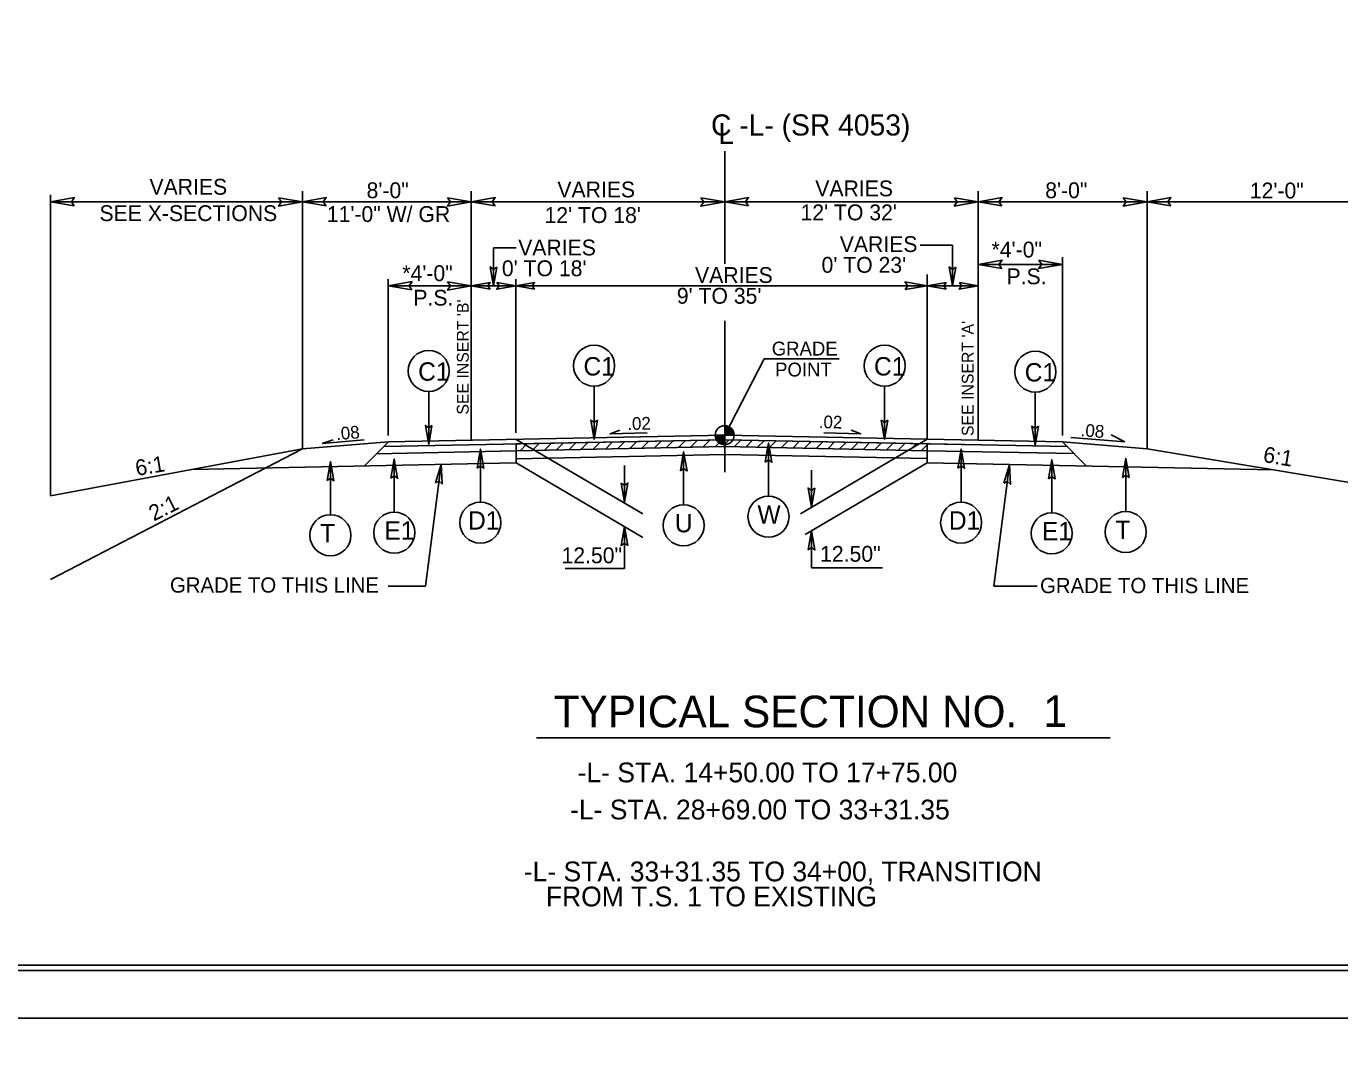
# Model space of a CAD drawing. Extents: x 981824 to 982276, y 44828 to 45204.
# Drawn here: x 982136.62 to 982186.38, y 45089.07 to 45127.55 of the extents above; entities that cross this region are included whole.
import ezdxf

# ---------------------------------------------------------------- set-up
doc = ezdxf.new("R2010")
doc.units = 0
for name, color, linetype in [('Default', 7, 'Continuous'), ('Old_Level_1', 7, 'Continuous'), ('Old_Level_11', 7, 'Continuous'), ('Old_Level_18', 7, 'Continuous'), ('Old_Level_2', 7, 'Continuous'), ('Old_Level_20', 7, 'Continuous'), ('Old_Level_21', 7, 'Continuous'), ('Old_Level_3', 7, 'Continuous'), ('Old_Level_50', 7, 'Continuous'), ('Old_Level_51', 7, 'Continuous'), ('Prop Dimension Text', 7, 'Continuous'), ('Prop Roadway Profile Bench Mark Info Text', 7, 'Continuous'), ('Typical Terminator CELL', 7, 'Continuous')]:
    doc.layers.add(name, color=color, linetype=linetype)

msp = doc.modelspace()

# ---------------------------------------------------------------- linework, layer by layer
at = {"layer": 'Default'}
for points in [[(982160.143, 45112.149), (982158.742, 45112.101), (982159.108, 45112.239)], [(982166.835, 45112.149), (982168.235, 45112.101), (982167.869, 45112.239)]]:
    msp.add_lwpolyline(points, dxfattribs=at)
at = {"layer": 'Old_Level_1'}
for p, q in [((982163.083, 45122.815), (982163.083, 45118.548)), ((982137.545, 45121.166), (982137.545, 45109.759)), ((982147.083, 45121.294), (982147.083, 45111.537)), ((982153.483, 45121.294), (982153.483, 45111.86)), ((982172.683, 45121.294), (982172.683, 45120.151)), ((982179.083, 45121.294), (982179.083, 45111.54)), ((982137.545, 45120.894), (982147.083, 45120.894)), ((982147.083, 45120.894), (982153.483, 45120.894)), ((982153.483, 45120.894), (982163.083, 45120.894)), ((982163.083, 45120.894), (982172.683, 45120.894)), ((982172.683, 45120.894), (982179.083, 45120.894)), ((982179.083, 45120.894), (982188.683, 45120.894)), ((982172.683, 45120.151), (982172.683, 45118.526)), ((982154.324, 45117.712), (982154.324, 45119.158)), ((982154.324, 45119.158), (982155.184, 45119.158)), ((982170.481, 45119.249), (982171.716, 45119.249)), ((982171.716, 45119.249), (982171.716, 45117.712)), ((982175.881, 45118.803), (982175.881, 45117.486)), ((982170.757, 45118.144), (982170.757, 45117.695)), ((982172.683, 45118.526), (982175.881, 45118.526)), ((982172.683, 45118.526), (982172.683, 45117.497)), ((982150.334, 45117.968), (982150.334, 45112.046)), ((982150.334, 45117.712), (982153.483, 45117.712)), ((982153.483, 45117.712), (982155.165, 45117.712)), ((982155.165, 45117.968), (982155.165, 45112.144)), ((982155.165, 45117.712), (982166.471, 45117.712)), ((982166.471, 45117.712), (982170.757, 45117.712)), ((982170.757, 45117.712), (982172.683, 45117.712)), ((982170.757, 45117.695), (982170.757, 45116.956)), ((982172.683, 45117.497), (982172.683, 45111.86)), ((982175.881, 45117.486), (982175.881, 45112.045)), ((982170.757, 45116.956), (982170.757, 45111.899)), ((982163.083, 45116.381), (982163.083, 45110.647)), ((982163.083, 45112.052), (982164.573, 45114.947)), ((982163.083, 45112.052), (982163.083, 45112.412)), ((982147.083, 45111.537), (982150.344, 45111.798)), ((982147.832, 45111.736), (982149.429, 45111.878)), ((982147.832, 45111.736), (982148.254, 45111.878)), ((982150.344, 45111.798), (982149.427, 45110.886)), ((982163.083, 45112.052), (982150.344, 45111.798)), ((982155.177, 45111.895), (982159.983, 45109.074)), ((982155.177, 45111.723), (982163.083, 45111.88)), ((982155.177, 45111.723), (982163.083, 45111.88)), ((982155.177, 45111.002), (982155.177, 45111.723)), ((982155.329, 45111.465), (982155.593, 45111.73)), ((982155.79, 45111.475), (982156.055, 45111.74)), ((982156.252, 45111.484), (982156.517, 45111.748)), ((982156.713, 45111.493), (982156.978, 45111.758)), ((982157.176, 45111.503), (982157.441, 45111.767)), ((982157.637, 45111.512), (982157.902, 45111.776)), ((982158.099, 45111.521), (982158.364, 45111.786)), ((982158.561, 45111.53), (982158.825, 45111.795)), ((982159.023, 45111.54), (982159.288, 45111.804)), ((982159.485, 45111.549), (982159.749, 45111.813)), ((982159.946, 45111.558), (982160.211, 45111.823)), ((982160.409, 45111.568), (982160.673, 45111.832)), ((982160.87, 45111.576), (982161.135, 45111.841)), ((982161.332, 45111.586), (982161.597, 45111.851)), ((982161.793, 45111.596), (982162.058, 45111.86)), ((982162.256, 45111.604), (982162.521, 45111.869)), ((982162.717, 45111.614), (982162.982, 45111.878)), ((982162.723, 45112.052), (982163.083, 45112.052)), ((982163.076, 45111.698), (982163.255, 45111.878)), ((982163.082, 45111.692), (982163.083, 45112.052)), ((982163.083, 45112.052), (982163.082, 45111.692)), ((982163.083, 45112.052), (982175.881, 45111.796)), ((982163.443, 45112.052), (982163.083, 45112.052)), ((982163.083, 45111.88), (982172.683, 45111.688)), ((982163.443, 45111.613), (982163.699, 45111.868)), ((982163.887, 45111.604), (982164.142, 45111.86)), ((982164.33, 45111.595), (982164.586, 45111.851)), ((982164.774, 45111.586), (982165.03, 45111.842)), ((982165.217, 45111.577), (982165.473, 45111.833)), ((982165.661, 45111.568), (982165.917, 45111.824)), ((982170.757, 45111.899), (982165.951, 45109.078)), ((982166.105, 45111.56), (982166.361, 45111.816)), ((982166.549, 45111.551), (982166.805, 45111.807)), ((982166.993, 45111.542), (982167.248, 45111.797)), ((982167.436, 45111.533), (982167.692, 45111.788)), ((982167.88, 45111.524), (982168.136, 45111.78)), ((982168.323, 45111.515), (982168.579, 45111.771)), ((982168.767, 45111.506), (982169.023, 45111.762)), ((982169.21, 45111.497), (982169.466, 45111.753)), ((982169.654, 45111.488), (982169.91, 45111.744)), ((982170.098, 45111.48), (982170.353, 45111.736)), ((982170.541, 45111.471), (982170.757, 45111.685)), ((982170.757, 45111.007), (982170.757, 45111.727)), ((982170.757, 45111.466), (982170.757, 45111.727)), ((982175.881, 45111.796), (982179.083, 45111.54)), ((982175.881, 45111.796), (982176.792, 45110.886)), ((982178.235, 45111.806), (982176.197, 45111.969)), ((982178.235, 45111.806), (982177.725, 45112.061)), ((982137.545, 45106.58), (982147.083, 45111.537)), ((982137.545, 45109.759), (982147.083, 45111.537)), ((982155.177, 45111.462), (982149.894, 45111.351)), ((982163.089, 45111.621), (982155.171, 45111.462)), ((982163.094, 45111.324), (982155.177, 45111.164)), ((982163.069, 45111.323), (982170.757, 45111.168)), ((982163.074, 45111.62), (982170.757, 45111.466)), ((982170.757, 45111.466), (982176.323, 45111.355)), ((982179.083, 45111.54), (982188.683, 45109.944)), ((982155.181, 45111.002), (982142.882, 45110.754)), ((982151.748, 45106.333), (982152.342, 45110.945)), ((982155.181, 45111.002), (982159.986, 45108.182)), ((982159.286, 45110.907), (982159.286, 45109.518)), ((982170.757, 45111.007), (982166.125, 45108.288)), ((982166.37, 45110.724), (982166.37, 45109.324)), ((982170.757, 45111.007), (982183.876, 45110.744)), ((982173.28, 45106.333), (982173.875, 45110.944)), ((982159.286, 45108.592), (982159.286, 45107.003)), ((982166.37, 45108.432), (982166.37, 45107.032)), ((982157.041, 45107.003), (982159.286, 45107.003)), ((982169.06, 45107.032), (982166.37, 45107.032)), ((982150.329, 45106.333), (982151.748, 45106.333)), ((982173.28, 45106.333), (982174.919, 45106.333))]:
    msp.add_line(p, q, dxfattribs=at)
for points in [[(982163.086, 45112.412), (982163.086, 45112.412), (982163.086, 45112.052)], [(982163.093, 45112.412), (982163.093, 45112.052)], [(982163.101, 45112.412), (982163.101, 45112.052)], [(982163.108, 45112.412), (982163.108, 45112.052)], [(982163.115, 45112.411), (982163.115, 45112.052)], [(982163.122, 45112.41), (982163.122, 45112.052)], [(982163.129, 45112.409), (982163.129, 45112.052)], [(982163.137, 45112.408), (982163.137, 45112.052)], [(982163.144, 45112.408), (982163.144, 45112.052)], [(982163.151, 45112.406), (982163.151, 45112.052)], [(982163.158, 45112.404), (982163.158, 45112.052)], [(982163.165, 45112.403), (982163.165, 45112.052)], [(982163.173, 45112.401), (982163.173, 45112.052)], [(982163.18, 45112.399), (982163.18, 45112.052)], [(982163.187, 45112.397), (982163.187, 45112.052)], [(982163.194, 45112.395), (982163.194, 45112.052)], [(982163.201, 45112.392), (982163.201, 45112.052)], [(982163.209, 45112.39), (982163.209, 45112.052)], [(982163.216, 45112.387), (982163.216, 45112.052)], [(982163.223, 45112.384), (982163.223, 45112.052)], [(982163.23, 45112.38), (982163.23, 45112.052)], [(982163.237, 45112.377), (982163.237, 45112.052)], [(982163.245, 45112.374), (982163.245, 45112.052)], [(982163.252, 45112.37), (982163.252, 45112.052)], [(982163.259, 45112.366), (982163.259, 45112.052)], [(982163.266, 45112.362), (982163.266, 45112.052)], [(982163.273, 45112.358), (982163.273, 45112.052)], [(982163.281, 45112.353), (982163.281, 45112.052)], [(982163.288, 45112.348), (982163.288, 45112.052)], [(982163.295, 45112.343), (982163.295, 45112.052)], [(982163.302, 45112.338), (982163.302, 45112.052)], [(982163.309, 45112.332), (982163.309, 45112.052)], [(982163.317, 45112.326), (982163.317, 45112.052)], [(982163.324, 45112.32), (982163.324, 45112.052)], [(982163.331, 45112.313), (982163.331, 45112.052)], [(982163.338, 45112.306), (982163.338, 45112.052)], [(982163.345, 45112.299), (982163.345, 45112.052)], [(982163.353, 45112.291), (982163.353, 45112.052)], [(982163.36, 45112.282), (982163.36, 45112.052)], [(982163.367, 45112.273), (982163.367, 45112.052)], [(982163.374, 45112.264), (982163.374, 45112.052)], [(982163.381, 45112.253), (982163.381, 45112.052)], [(982163.389, 45112.242), (982163.389, 45112.052)], [(982163.396, 45112.23), (982163.396, 45112.052)], [(982163.403, 45112.217), (982163.403, 45112.052)], [(982163.41, 45112.202), (982163.41, 45112.052)], [(982163.417, 45112.185), (982163.417, 45112.052)], [(982162.725, 45112.052), (982162.725, 45112.013)], [(982162.732, 45112.052), (982162.732, 45111.971)], [(982162.739, 45112.052), (982162.739, 45111.945)], [(982162.746, 45112.052), (982162.746, 45111.924)], [(982162.753, 45112.052), (982162.753, 45111.907)], [(982162.761, 45112.052), (982162.761, 45111.892)], [(982162.768, 45112.052), (982162.768, 45111.878)], [(982162.775, 45112.052), (982162.775, 45111.865)], [(982162.782, 45112.052), (982162.782, 45111.854)], [(982162.789, 45112.052), (982162.789, 45111.844)], [(982162.797, 45112.052), (982162.797, 45111.834)], [(982162.804, 45112.052), (982162.804, 45111.825)], [(982162.811, 45112.052), (982162.811, 45111.816)], [(982162.818, 45112.052), (982162.818, 45111.808)], [(982162.825, 45112.052), (982162.825, 45111.8)], [(982162.833, 45112.052), (982162.833, 45111.793)], [(982162.84, 45112.052), (982162.84, 45111.787)], [(982162.847, 45112.052), (982162.847, 45111.78)], [(982162.854, 45112.052), (982162.854, 45111.774)], [(982162.861, 45112.052), (982162.861, 45111.768)], [(982162.869, 45112.052), (982162.869, 45111.763)], [(982162.876, 45112.052), (982162.876, 45111.758)], [(982162.883, 45112.052), (982162.883, 45111.753)], [(982162.89, 45112.052), (982162.89, 45111.748)], [(982162.897, 45112.052), (982162.897, 45111.744)], [(982162.905, 45112.052), (982162.905, 45111.74)], [(982162.912, 45112.052), (982162.912, 45111.736)], [(982162.919, 45112.052), (982162.919, 45111.732)], [(982162.926, 45112.052), (982162.926, 45111.728)], [(982162.933, 45112.052), (982162.933, 45111.725)], [(982162.941, 45112.052), (982162.941, 45111.722)], [(982162.948, 45112.052), (982162.948, 45111.719)], [(982162.955, 45112.052), (982162.955, 45111.716)], [(982162.962, 45112.052), (982162.962, 45111.713)], [(982162.969, 45112.052), (982162.969, 45111.711)], [(982162.977, 45112.052), (982162.977, 45111.708)], [(982162.984, 45112.052), (982162.984, 45111.707)], [(982162.991, 45112.052), (982162.991, 45111.704)], [(982162.998, 45112.052), (982162.998, 45111.703)], [(982163.005, 45112.052), (982163.005, 45111.701)], [(982163.013, 45112.052), (982163.013, 45111.7)], [(982163.02, 45112.052), (982163.02, 45111.698)], [(982163.027, 45112.052), (982163.027, 45111.697)], [(982163.034, 45112.052), (982163.034, 45111.696)], [(982163.041, 45112.052), (982163.041, 45111.695)], [(982163.049, 45112.052), (982163.049, 45111.694)], [(982163.056, 45112.052), (982163.056, 45111.693)], [(982163.063, 45112.052), (982163.063, 45111.693)], [(982163.07, 45112.052), (982163.07, 45111.692)], [(982163.077, 45112.052), (982163.077, 45111.692), (982163.077, 45111.692)], [(982163.425, 45112.165), (982163.425, 45112.052)], [(982163.432, 45112.14), (982163.432, 45112.052)], [(982163.439, 45112.104), (982163.439, 45112.052)]]:
    msp.add_lwpolyline(points, dxfattribs=at)
for points in [[(982155.177, 45111.462), (982163.089, 45111.621), (982163.083, 45111.88), (982155.177, 45111.723)], [(982163.074, 45111.62), (982170.757, 45111.466), (982170.757, 45111.727), (982163.08, 45111.881)]]:
    msp.add_lwpolyline(points, close=True, dxfattribs=at)
msp.add_circle((982163.082, 45112.053), 0.36, dxfattribs=at)
for start, end in [(359.9905, 89.9905), (179.9905, 269.9905)]:
    msp.add_arc((982163.082, 45112.053), 0.36, start, end, dxfattribs=at)
at = {"layer": 'Old_Level_11'}
for points in [[(982169.916, 45117.568), (982170.757, 45117.712), (982169.911, 45117.862), (982170.018, 45117.712)], [(982151.994, 45112.422), (982151.87, 45111.702), (982151.742, 45112.426), (982151.87, 45112.334)], [(982158.259, 45112.618), (982158.135, 45111.898), (982158.007, 45112.622), (982158.135, 45112.53)], [(982169.264, 45112.618), (982169.14, 45111.898), (982169.012, 45112.622), (982169.14, 45112.53)], [(982174.974, 45112.392), (982174.85, 45111.672), (982174.722, 45112.396), (982174.85, 45112.304)], [(982164.619, 45111.035), (982164.743, 45111.755), (982164.871, 45111.031), (982164.743, 45111.123)], [(982153.703, 45110.808), (982153.827, 45111.528), (982153.955, 45110.804), (982153.827, 45110.896)], [(982161.403, 45110.706), (982161.527, 45111.426), (982161.655, 45110.702), (982161.527, 45110.794)], [(982171.916, 45110.808), (982172.04, 45111.528), (982172.168, 45110.804), (982172.04, 45110.896)], [(982178.149, 45110.456), (982178.273, 45111.176), (982178.401, 45110.452), (982178.273, 45110.544)], [(982148.024, 45110.331), (982148.148, 45111.051), (982148.276, 45110.327), (982148.148, 45110.419)], [(982150.44, 45110.429), (982150.564, 45111.149), (982150.692, 45110.425), (982150.564, 45110.517)], [(982175.347, 45110.402), (982175.471, 45111.122), (982175.599, 45110.398), (982175.471, 45110.49)]]:
    msp.add_lwpolyline(points, close=True, dxfattribs=at)
at = {"layer": 'Old_Level_18'}
msp.add_lwpolyline([(982227.72, 45175.969), (982107.72, 45175.969), (982107.72, 45091.969), (982227.72, 45091.969)], close=True, dxfattribs=at)
at = {"layer": 'Old_Level_21'}
for points in [[(982163.083, 45111.88), (982150.168, 45111.623), (982150.344, 45111.798), (982163.083, 45112.052)], [(982163.083, 45112.052), (982175.881, 45111.796), (982176.057, 45111.621), (982163.08, 45111.88)]]:
    msp.add_lwpolyline(points, close=True, dxfattribs=at)
at = {"layer": 'Old_Level_3'}
msp.add_line((982164.573, 45114.947), (982167.419, 45114.947), dxfattribs=at)
at = {"layer": 'Old_Level_50'}
msp.add_lwpolyline([(982228.72, 45176.173), (982095.4, 45176.173), (982095.4, 45091.765), (982228.72, 45091.765)], close=True, dxfattribs=at)
at = {"layer": 'Old_Level_51'}
for points in [[(982229.08, 45177.969), (982094.36, 45177.969), (982094.36, 45089.969), (982229.08, 45089.969)], [(982229.08, 45089.969), (982094.36, 45089.969), (982094.36, 45001.969), (982229.08, 45001.969)]]:
    msp.add_lwpolyline(points, close=True, dxfattribs=at)
at = {"layer": 'Prop Dimension Text'}
for p, q in [((982151.87, 45113.711), (982151.87, 45111.702)), ((982158.135, 45113.908), (982158.135, 45111.898)), ((982169.14, 45113.908), (982169.14, 45111.898)), ((982174.85, 45113.681), (982174.85, 45111.672)), ((982164.743, 45109.745), (982164.743, 45111.755)), ((982153.827, 45109.519), (982153.827, 45111.528)), ((982161.527, 45109.416), (982161.527, 45111.426)), ((982172.04, 45109.519), (982172.04, 45111.528)), ((982178.273, 45109.166), (982178.273, 45111.176)), ((982148.148, 45109.041), (982148.148, 45111.051)), ((982150.564, 45109.139), (982150.564, 45111.149)), ((982175.471, 45109.112), (982175.471, 45111.122))]:
    msp.add_line(p, q, dxfattribs=at)
for centre in [(982151.87, 45114.488), (982158.135, 45114.685), (982169.14, 45114.685), (982174.85, 45114.459), (982164.742, 45108.967), (982153.826, 45108.74), (982161.526, 45108.637), (982172.039, 45108.74), (982148.146, 45108.263), (982150.563, 45108.361), (982175.47, 45108.335), (982178.272, 45108.388)]:
    msp.add_circle(centre, 0.778, dxfattribs=at)
at = {"layer": 'Prop Roadway Profile Bench Mark Info Text'}
msp.add_line((982155.959, 45100.582), (982177.679, 45100.582), dxfattribs=at)
at = {"layer": 'Typical Terminator CELL'}
for points in [[(982138.445, 45120.739), (982137.545, 45120.894), (982138.45, 45121.054), (982138.335, 45120.894)], [(982146.183, 45121.049), (982147.083, 45120.894), (982146.178, 45120.734), (982146.293, 45120.894)], [(982147.983, 45120.739), (982147.083, 45120.894), (982147.988, 45121.054), (982147.873, 45120.894)], [(982152.583, 45121.049), (982153.483, 45120.894), (982152.578, 45120.734), (982152.693, 45120.894)], [(982154.383, 45120.739), (982153.483, 45120.894), (982154.388, 45121.054), (982154.273, 45120.894)], [(982162.183, 45121.049), (982163.083, 45120.894), (982162.178, 45120.734), (982162.293, 45120.894)], [(982163.983, 45120.739), (982163.083, 45120.894), (982163.988, 45121.054), (982163.873, 45120.894)], [(982171.783, 45121.049), (982172.683, 45120.894), (982171.778, 45120.734), (982171.893, 45120.894)], [(982173.583, 45120.739), (982172.683, 45120.894), (982173.588, 45121.054), (982173.473, 45120.894)], [(982178.183, 45121.049), (982179.083, 45120.894), (982178.178, 45120.734), (982178.293, 45120.894)], [(982179.983, 45120.739), (982179.083, 45120.894), (982179.988, 45121.054), (982179.873, 45120.894)], [(982173.583, 45118.371), (982172.683, 45118.526), (982173.588, 45118.686), (982173.473, 45118.526)], [(982174.981, 45118.681), (982175.881, 45118.526), (982174.976, 45118.366), (982175.091, 45118.526)], [(982154.446, 45118.424), (982154.324, 45117.712), (982154.197, 45118.428), (982154.324, 45118.337)], [(982171.838, 45118.424), (982171.716, 45117.712), (982171.589, 45118.428), (982171.716, 45118.337)], [(982151.234, 45117.557), (982150.334, 45117.712), (982151.239, 45117.872), (982151.124, 45117.712)], [(982152.583, 45117.867), (982153.483, 45117.712), (982152.578, 45117.552), (982152.693, 45117.712)], [(982154.194, 45117.59), (982153.483, 45117.712), (982154.198, 45117.839), (982154.107, 45117.712)], [(982154.453, 45117.835), (982155.165, 45117.712), (982154.449, 45117.586), (982154.54, 45117.712)], [(982155.876, 45117.59), (982155.165, 45117.712), (982155.88, 45117.839), (982155.789, 45117.712)], [(982171.468, 45117.59), (982170.757, 45117.712), (982171.472, 45117.839), (982171.381, 45117.712)], [(982171.972, 45117.835), (982172.683, 45117.712), (982171.968, 45117.586), (982172.059, 45117.712)], [(982152.129, 45110.246), (982152.342, 45110.944), (982152.379, 45110.21), (982152.263, 45110.317)], [(982173.66, 45110.232), (982173.873, 45110.931), (982173.909, 45110.197), (982173.794, 45110.304)], [(982159.162, 45110.238), (982159.286, 45109.518), (982159.414, 45110.242), (982159.286, 45110.15)], [(982166.494, 45110.044), (982166.37, 45109.324), (982166.242, 45110.048), (982166.37, 45109.956)], [(982159.41, 45107.872), (982159.286, 45108.592), (982159.158, 45107.868), (982159.286, 45107.96)], [(982166.246, 45107.712), (982166.37, 45108.432), (982166.498, 45107.708), (982166.37, 45107.8)]]:
    msp.add_lwpolyline(points, close=True, dxfattribs=at)

# ---------------------------------------------------------------- texts
at = {"layer": 'Old_Level_1'}
for s, height, p in [('C -L- (SR 4053)', 0.8, (982162.566, 45123.408)), ('L', 0.8, (982162.84, 45123.082)), ('VARIES', 0.6, (982141.292, 45121.166)), ('8\'-0"', 0.6, (982149.516, 45121.033)), ('VARIES', 0.6, (982156.744, 45121.064)), ('VARIES', 0.6, (982166.514, 45121.105)), ('8\'-0"', 0.6, (982175.225, 45121.033)), ('12\'-0"', 0.6, (982182.975, 45121.024)), ('SEE X-SECTIONS', 0.6, (982139.398, 45120.166)), ('11\'-0" W/ GR', 0.6, (982148.01, 45120.132)), ("12' TO 18'", 0.6, (982156.257, 45120.094)), ("12' TO 32'", 0.6, (982165.955, 45120.195)), ('VARIES', 0.6, (982155.26, 45118.865)), ('VARIES', 0.6, (982167.442, 45118.994)), ('*4\'-0"', 0.6, (982173.192, 45118.787)), ("0' TO 18'", 0.6, (982154.642, 45118.078)), ("0' TO 23'", 0.6, (982166.752, 45118.207)), ('*4\'-0"', 0.6, (982150.87, 45117.892)), ('VARIES', 0.6, (982161.959, 45117.821)), ('P.S.', 0.6, (982173.758, 45117.773)), ("9' TO 35'", 0.6, (982161.269, 45117.035)), ('P.S.', 0.6, (982151.289, 45116.963)), ('12.50"', 0.6, (982156.901, 45107.202)), ('12.50"', 0.6, (982166.697, 45107.258))]:
    msp.add_text(s, height=height, dxfattribs=at).set_placement(p)
for s, height, rotation, p in [("SEE INSERT 'B'", 0.4485, 90, (982153.385, 45112.833)), ("SEE INSERT 'A'", 0.4485, 90, (982172.512, 45112.022)), ('6:1', 0.6, 9.4617, (982140.808, 45110.508)), ('6:1', 0.6, 350.5609, (982183.451, 45111.042)), ('2:1', 0.6, 26.5646, (982141.457, 45108.783))]:
    msp.add_text(s, height=height, rotation=rotation, dxfattribs=at).set_placement(p)
at = {"layer": 'Old_Level_2'}
for s, rotation, p in [('.02  ', 1.144, (982159.396, 45112.251)), ('.02  ', 358.856, (982166.642, 45112.322)), ('.08', 4.5739, (982148.381, 45111.867)), ('.08', 355.4261, (982176.553, 45112.017))]:
    msp.add_text(s, height=0.48, rotation=rotation, dxfattribs=at).set_placement(p)
at = {"layer": 'Old_Level_20'}
for s, p in [('C1', (982151.469, 45114.118)), ('C1', (982157.733, 45114.315)), ('C1', (982168.738, 45114.315)), ('C1', (982174.448, 45114.089)), ('W', (982164.323, 45108.703)), ('T ', (982147.755, 45107.998)), ('E1', (982150.191, 45108.097)), ('D1', (982153.36, 45108.476)), ('U', (982161.195, 45108.374)), ('D1', (982171.573, 45108.476)), ('E1', (982175.098, 45108.07)), ('T ', (982177.88, 45108.123))]:
    msp.add_text(s, height=0.696, dxfattribs=at).set_placement(p)
at = {"layer": 'Old_Level_3'}
for s, height, p in [('GRADE TO THIS LINE', 0.576, (982142.069, 45106.088)), ('TYPICAL SECTION NO.  ', 1.2, (982156.603, 45100.985)), ('1 ', 1.2, (982175.155, 45101.001))]:
    msp.add_text(s, height=height, dxfattribs=at).set_placement(p)
at = {"layer": 'Prop Dimension Text'}
for s, height, p in [('GRADE', 0.5248, (982164.866, 45115.073)), ('POINT', 0.5248, (982164.993, 45114.278)), ('GRADE TO THIS LINE', 0.576, (982175.029, 45106.068)), ('-L- STA. 14+50.00 TO 17+75.00', 0.75, (982157.51, 45098.901)), (' -L- STA. 28+69.00 TO 33+31.35', 0.75, (982156.946, 45097.494)), (' -L- STA. 33+31.35 TO 34+00, TRANSITION', 0.75, (982155.194, 45095.149)), ('    FROM T.S. 1 TO EXISTING', 0.75, (982155.194, 45094.199))]:
    msp.add_text(s, height=height, dxfattribs=at).set_placement(p)

doc.saveas('drawing.dxf')
